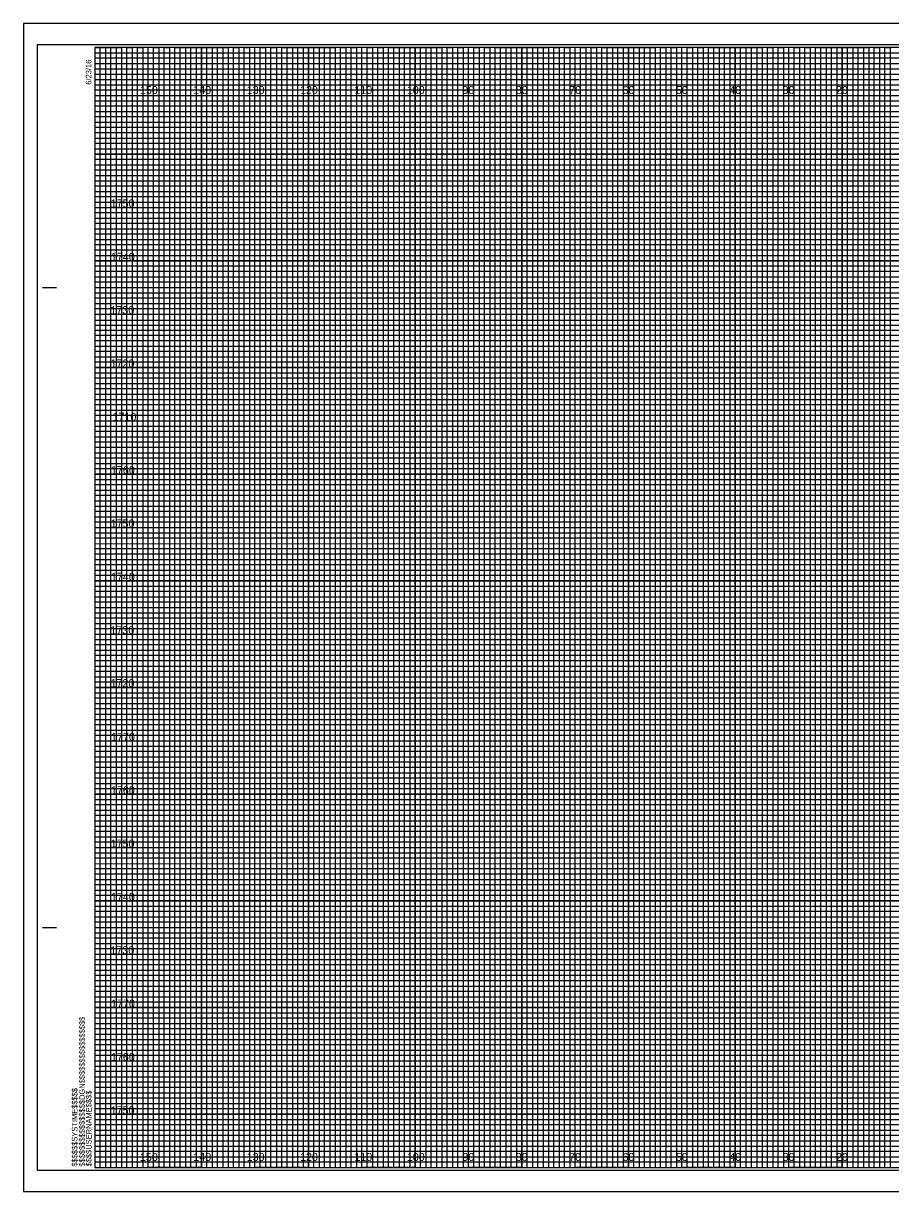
# Model space of a CAD drawing. Extents: x 570 to 907, y -9 to 870.
# Drawn here: x 570.4 to 732.9, y -9.4 to 209.6 of the extents above; entities that cross this region are included whole.
import ezdxf

# ---------------------------------------------------------------- set-up
doc = ezdxf.new("R2010")
doc.units = 0
for name, color, linetype in [('Prop XS Earthwork Shape', 7, 'Continuous'), ('Raster_Level_0', 7, 'Continuous'), ('Scratch_Level_3', 7, 'Continuous'), ('Sheet Cross Section CELL', 7, 'Continuous'), ('Sheet Cross Section Grid Middle CELL', 7, 'Continuous'), ('Sheet Cross Section Grid Minor 1 CELL', 7, 'Continuous'), ('Sheet Cross Section Grid Minor 2 CELL', 7, 'Continuous'), ('Sheet Cutting Line CELL', 7, 'Continuous'), ('Sheet DOT Grid CELL', 7, 'Continuous'), ('Sheet Plot Border Inside CELL', 7, 'Continuous'), ('Sheet Plot Border Outside CELL', 7, 'Continuous')]:
    doc.layers.add(name, color=color, linetype=linetype)

msp = doc.modelspace()

# ---------------------------------------------------------------- linework, layer by layer
at = {"layer": 'Prop XS Earthwork Shape'}
for p, q in [((593.77, 205.14), (583.77, 205.14)), ((593.77, -4.86), (593.77, 205.14)), ((613.77, 205.14), (603.77, 205.14)), ((603.77, 205.14), (603.77, -4.86)), ((613.77, -4.86), (613.77, 205.14)), ((633.77, 205.14), (623.77, 205.14)), ((623.77, 205.14), (623.77, -4.86)), ((633.77, -4.86), (633.77, 205.14)), ((653.77, 205.14), (643.77, 205.14)), ((643.77, 205.14), (643.77, -4.86)), ((653.77, -4.86), (653.77, 205.14)), ((673.77, 205.14), (663.77, 205.14)), ((663.77, 205.14), (663.77, -4.86)), ((673.77, -4.86), (673.77, 205.14)), ((693.77, 205.14), (683.77, 205.14)), ((683.77, 205.14), (683.77, -4.86)), ((693.77, -4.86), (693.77, 205.14)), ((713.77, 205.14), (703.77, 205.14)), ((703.77, 205.14), (703.77, -4.86)), ((713.77, -4.86), (713.77, 205.14)), ((733.77, 205.14), (723.77, 205.14)), ((723.77, 205.14), (723.77, -4.86)), ((603.77, -4.86), (593.77, -4.86)), ((623.77, -4.86), (613.77, -4.86)), ((643.77, -4.86), (633.77, -4.86)), ((663.77, -4.86), (653.77, -4.86)), ((683.77, -4.86), (673.77, -4.86)), ((703.77, -4.86), (693.77, -4.86)), ((723.77, -4.86), (713.77, -4.86))]:
    msp.add_line(p, q, dxfattribs=at)
for points in [[(583.77, 195.14), (903.77, 195.14), (903.77, 185.14), (583.77, 185.14)], [(583.77, 175.14), (903.77, 175.14), (903.77, 165.14), (583.77, 165.14)], [(583.77, 155.14), (903.77, 155.14), (903.77, 145.14), (583.77, 145.14)], [(583.77, 135.14), (903.77, 135.14), (903.77, 125.14), (583.77, 125.14)], [(583.77, 115.14), (903.77, 115.14), (903.77, 105.14), (583.77, 105.14)], [(583.77, 95.14), (903.77, 95.14), (903.77, 85.14), (583.77, 85.14)], [(583.77, 75.14), (903.77, 75.14), (903.77, 65.14), (583.77, 65.14)], [(583.77, 55.14), (903.77, 55.14), (903.77, 45.14), (583.77, 45.14)], [(583.77, 35.14), (903.77, 35.14), (903.77, 25.14), (583.77, 25.14)], [(583.77, 15.14), (903.77, 15.14), (903.77, 5.14), (583.77, 5.14)]]:
    msp.add_lwpolyline(points, dxfattribs=at)
at = {"layer": 'Sheet Cross Section CELL'}
for p, q in [((573.97, 160.14), (576.47, 160.14)), ((574.07, 160.14), (576.57, 160.14)), ((573.97, 40.14), (576.47, 40.14)), ((574.07, 40.14), (576.57, 40.14)), ((583.77, -4.86), (583.77, -4.86)), ((583.77, -4.86), (583.77, -4.86)), ((583.77, -4.86), (583.77, -4.86)), ((583.77, -4.86), (583.77, -4.86)), ((583.77, -4.86), (583.77, -4.86)), ((583.77, -4.86), (583.77, -4.86)), ((583.77, -4.86), (583.77, -4.86))]:
    msp.add_line(p, q, dxfattribs=at)
msp.add_lwpolyline([(903.77, 205.14), (583.77, 205.14), (583.77, -4.86), (903.77, -4.86)], close=True, dxfattribs=at)
at = {"layer": 'Sheet Cross Section Grid Middle CELL'}
for points in [[(583.77, 205.14), (588.77, 205.14), (588.77, -4.86), (598.77, -4.86), (598.77, 205.14), (608.77, 205.14), (608.77, -4.86), (618.77, -4.86), (618.77, 205.14), (628.77, 205.14), (628.77, -4.86), (638.77, -4.86), (638.77, 205.14), (648.77, 205.14), (648.77, -4.86), (658.77, -4.86), (658.77, 205.14), (668.77, 205.14), (668.77, -4.86), (678.77, -4.86), (678.77, 205.14), (688.77, 205.14), (688.77, -4.86), (698.77, -4.86), (698.77, 205.14), (708.77, 205.14), (708.77, -4.86), (718.77, -4.86), (718.77, 205.14), (728.77, 205.14), (728.77, -4.86), (738.77, -4.86)], [(583.77, 200.14), (858.77, 200.14)], [(583.77, 180.14), (903.77, 180.14), (903.77, 190.14), (583.77, 190.14)], [(583.77, 160.14), (903.77, 160.14), (903.77, 170.14), (583.77, 170.14)], [(583.77, 140.14), (903.77, 140.14), (903.77, 150.14), (583.77, 150.14)], [(583.77, 120.14), (903.77, 120.14), (903.77, 130.14), (583.77, 130.14)], [(583.77, 100.14), (903.77, 100.14), (903.77, 110.14), (583.77, 110.14)], [(583.77, 80.14), (903.77, 80.14), (903.77, 90.14), (583.77, 90.14)], [(583.77, 60.14), (903.77, 60.14), (903.77, 70.14), (583.77, 70.14)], [(583.77, 40.14), (903.77, 40.14), (903.77, 50.14), (583.77, 50.14)], [(583.77, 20.14), (903.77, 20.14), (903.77, 30.14), (583.77, 30.14)], [(583.77, 0.14), (903.77, 0.14), (903.77, 10.14), (583.77, 10.14)]]:
    msp.add_lwpolyline(points, dxfattribs=at)
at = {"layer": 'Sheet Cross Section Grid Minor 1 CELL'}
for p, q in [((583.77, 204.14), (843.77, 204.14)), ((843.77, 203.12), (583.77, 203.12)), ((583.77, 203.12), (583.77, 202.14)), ((583.77, 202.14), (843.77, 202.14)), ((843.77, 201.03), (583.77, 201.03)), ((583.77, 201.03), (583.77, 199.14)), ((583.77, 199.14), (903.77, 199.14))]:
    msp.add_line(p, q, dxfattribs=at)
for points in [[(583.77, 198.14), (853.77, 198.14), (903.77, 198.14), (903.77, 197.14), (583.77, 197.14)], [(583.77, 196.14), (903.77, 196.14), (903.77, 194.14), (583.77, 194.14)], [(583.77, 193.14), (903.77, 193.14), (903.77, 192.14), (583.77, 192.12)], [(583.77, 191.14), (903.77, 191.14), (903.77, 189.14), (583.77, 189.14)], [(583.77, 188.14), (903.77, 188.14), (903.77, 187.14), (583.77, 187.14)], [(583.77, 186.14), (903.77, 186.14), (903.77, 184.14), (583.77, 184.14)], [(583.77, 183.14), (903.77, 183.14), (903.77, 182.14), (583.77, 182.14)], [(583.77, 181.14), (903.77, 181.14), (903.77, 179.14), (583.77, 179.14)], [(583.77, 178.14), (903.77, 178.14), (903.77, 177.14), (583.77, 177.14)], [(583.77, 176.14), (903.77, 176.14), (903.77, 174.14), (583.77, 174.14)], [(583.77, 173.14), (903.77, 173.14), (903.77, 172.14), (583.77, 172.14)], [(583.77, 171.14), (903.77, 171.14), (903.77, 169.09), (903.77, 168.14), (903.77, 167.14), (583.77, 167.14)], [(583.77, 169.14), (903.77, 169.14), (903.77, 168.14), (583.77, 168.14)], [(583.77, 166.14), (903.77, 166.14), (903.77, 164.14), (583.77, 164.17)], [(583.77, 164.17), (903.77, 164.14), (903.77, 163.14), (583.77, 163.14)], [(583.77, 162.14), (903.77, 162.14), (903.77, 161.14), (583.77, 161.14)], [(583.77, 159.14), (903.77, 159.14), (903.77, 158.14), (583.77, 158.14)], [(583.77, 157.14), (903.77, 157.14), (903.77, 156.14), (583.77, 156.14)], [(583.7, 154.03), (903.77, 154.03), (903.77, 153.02), (583.7, 153.02)], [(583.77, 152.14), (903.77, 152.14), (903.77, 151.14), (583.77, 151.14)], [(583.77, 149.14), (903.77, 149.14), (903.77, 148.14), (583.77, 148.14)], [(583.77, 147.14), (903.77, 147.14), (903.77, 146.14), (583.77, 146.14)], [(583.77, 144.14), (903.77, 144.14), (903.77, 143.14), (583.77, 143.14)], [(583.77, 142.14), (903.77, 142.14), (903.77, 141.14), (583.77, 141.14)], [(583.77, 139.14), (903.77, 139.14), (903.77, 138.14), (583.77, 138.14)], [(583.77, 137.14), (903.77, 137.14), (903.77, 136.14), (583.77, 136.14)], [(583.77, 134.14), (903.77, 134.14), (903.76, 133.12), (583.77, 133.14)], [(583.77, 132.14), (903.77, 132.14), (903.77, 131.14), (583.77, 131.14)], [(583.77, 129.14), (903.77, 129.14), (903.77, 128.14), (583.77, 128.14)], [(583.77, 127.14), (903.77, 127.14), (903.77, 126.14), (583.77, 126.14)], [(583.77, 124.14), (903.77, 124.14), (903.77, 123.14), (583.77, 123.14)], [(583.77, 122.14), (903.77, 122.14), (903.77, 121.14), (583.77, 121.14)], [(583.77, 119.14), (903.77, 119.14), (903.77, 118.14), (583.77, 118.14)], [(583.77, 117.14), (903.77, 117.14), (903.77, 116.14), (583.77, 116.14)], [(583.77, 114.14), (903.77, 114.14), (903.77, 113.14), (583.77, 113.14)], [(583.77, 112.13), (903.84, 112.05), (903.77, 111.14), (583.77, 111.14)], [(583.77, 109.14), (903.77, 109.14), (903.77, 108.14), (583.77, 108.14)], [(583.77, 107.14), (903.77, 107.14), (903.77, 106.14), (583.77, 106.14)], [(583.77, 104.14), (903.77, 104.14), (903.77, 103.14), (583.77, 103.14)], [(583.77, 102.14), (903.77, 102.14), (903.77, 101.14), (583.77, 101.14)], [(583.77, 99.14), (903.77, 99.14), (903.77, 98.14), (583.77, 98.14)], [(583.77, 97.14), (903.77, 97.14), (903.77, 96.14), (583.77, 96.14)], [(583.77, 94.14), (903.77, 94.14), (903.77, 93.14), (583.77, 93.14)], [(583.77, 92.14), (903.77, 92.14), (903.77, 91.14), (583.77, 91.14)], [(583.77, 89.14), (903.77, 89.14), (903.77, 88.14), (583.77, 88.14)], [(583.77, 87.14), (903.77, 87.14), (903.77, 86.14), (583.77, 86.14)], [(583.77, 84.14), (903.77, 84.14), (903.77, 83.14), (583.77, 83.14)], [(583.77, 82.14), (903.77, 82.14), (903.77, 81.14), (583.77, 81.14)], [(583.77, 79.14), (903.77, 79.14), (903.77, 78.14), (583.77, 78.14)], [(583.77, 77.14), (903.77, 77.14), (903.77, 76.14), (583.77, 76.14)], [(583.77, 74.14), (903.77, 74.14), (903.76, 73.12), (583.77, 73.14)], [(583.77, 72.14), (903.77, 72.14), (903.77, 71.14), (583.77, 71.14)], [(583.77, 69.14), (903.77, 69.14), (903.77, 68.14), (583.77, 68.14)], [(583.77, 67.14), (903.77, 67.14), (903.77, 66.14), (583.77, 66.14)], [(583.77, 64.14), (903.77, 64.14), (903.77, 63.14), (583.77, 63.14)], [(583.77, 62.14), (903.77, 62.14), (903.77, 61.14), (583.77, 61.14)], [(583.77, 59.14), (903.77, 59.14), (903.77, 58.14), (583.77, 58.14)], [(583.77, 57.14), (903.77, 57.14), (903.77, 56.14), (583.77, 56.14)], [(583.77, 54.14), (903.77, 54.14), (903.77, 53.14), (583.77, 53.14)], [(583.77, 52.13), (903.84, 52.05), (903.77, 51.14), (583.77, 51.14)], [(583.77, 49.14), (903.77, 49.14), (903.77, 48.14), (583.77, 48.14)], [(583.77, 47.14), (903.77, 47.14), (903.77, 46.14), (583.77, 46.14)], [(583.77, 44.14), (903.77, 44.14), (903.77, 43.14), (583.77, 43.14)], [(583.77, 42.14), (903.77, 42.14), (903.77, 41.14), (583.77, 41.14)], [(583.77, 39.14), (903.77, 39.14), (903.77, 38.14), (583.77, 38.14)], [(583.77, 37.14), (903.77, 37.14), (903.77, 36.14), (583.77, 36.14)], [(583.77, 34.14), (903.77, 34.14), (903.77, 33.14), (583.77, 33.14)], [(583.77, 32.14), (903.77, 32.14), (903.77, 31.14), (583.77, 31.14)], [(583.77, 29.14), (903.77, 29.14), (903.77, 28.14), (583.77, 28.14)], [(583.77, 27.14), (903.77, 27.14), (903.77, 26.14), (583.77, 26.14)], [(583.77, 24.14), (903.77, 24.14), (903.77, 23.14), (583.77, 23.14)], [(583.77, 22.14), (903.77, 22.14), (903.77, 21.14), (583.77, 21.14)], [(583.77, 19.14), (903.77, 19.14), (903.77, 18.14), (583.77, 18.14)], [(583.77, 17.14), (903.77, 17.14), (903.77, 16.14), (583.77, 16.14)], [(583.77, 14.14), (903.77, 14.14), (903.77, 13.14), (583.77, 13.14)], [(583.77, 12.14), (903.77, 12.14), (903.77, 11.14), (583.77, 11.14)], [(583.77, 9.14), (903.77, 9.14), (903.77, 8.14), (583.77, 8.14)], [(583.77, 7.14), (903.77, 7.14), (903.77, 6.14), (583.77, 6.14)], [(583.77, 4.14), (903.77, 4.14), (903.77, 3.14), (583.77, 3.14)], [(583.77, 2.14), (903.77, 2.14), (903.77, 1.14), (583.77, 1.14)], [(583.77, -0.86), (903.77, -0.86), (903.77, -1.86), (583.77, -1.86)], [(583.77, -2.86), (903.77, -2.86), (903.77, -3.86), (583.77, -3.86)]]:
    msp.add_lwpolyline(points, dxfattribs=at)
at = {"layer": 'Sheet Cross Section Grid Minor 2 CELL'}
for points in [[(583.77, -4.86), (584.77, -4.86), (584.77, 205.14), (585.77, 205.14), (585.77, -4.86)], [(585.77, -4.86), (586.77, -4.86), (586.77, 205.14), (587.77, 205.14), (587.77, -4.86)], [(588.77, -4.86), (589.77, -4.86), (589.77, 205.14), (590.77, 205.14), (590.77, -4.86)], [(590.77, -4.86), (591.77, -4.86), (591.77, 205.14), (592.77, 205.14), (592.77, -4.86)], [(593.77, -4.86), (594.77, -4.86), (594.77, 205.14), (595.77, 205.14), (595.77, -4.86)], [(595.77, -4.86), (596.77, -4.86), (596.77, 205.14), (597.77, 205.14), (597.77, -4.86)], [(598.77, -4.86), (599.77, -4.86), (599.77, 205.14), (600.77, 205.14), (600.77, -4.86)], [(600.77, -4.86), (601.77, -4.86), (601.77, 205.14), (602.77, 205.14), (602.77, -4.86)], [(603.77, -4.86), (604.77, -4.86), (604.77, 205.14), (605.77, 205.14), (605.77, -4.86)], [(605.77, -4.86), (606.77, -4.86), (606.77, 205.14), (607.77, 205.14), (607.77, -4.86)], [(608.77, -4.86), (609.77, -4.86), (609.77, 205.14), (610.77, 205.14), (610.77, -4.86)], [(610.77, -4.86), (611.77, -4.86), (611.77, 205.14), (612.77, 205.14), (612.77, -4.86)], [(613.77, -4.86), (614.77, -4.86), (614.77, 205.14), (615.77, 205.14), (615.77, -4.86)], [(615.77, -4.86), (616.77, -4.86), (616.77, 205.14), (617.77, 205.14), (617.77, -4.86)], [(618.77, -4.86), (619.77, -4.86), (619.77, 205.14), (620.77, 205.14), (620.77, -4.86)], [(620.77, -4.86), (621.77, -4.86), (621.77, 205.14), (622.77, 205.14), (622.77, -4.86)], [(623.77, -4.86), (624.77, -4.86), (624.77, 205.14), (625.77, 205.14), (625.77, -4.86)], [(625.77, -4.86), (626.77, -4.86), (626.77, 205.14), (627.77, 205.14), (627.77, -4.86)], [(628.77, -4.86), (629.77, -4.86), (629.77, 205.14), (630.77, 205.14), (630.77, -4.86)], [(630.77, -4.86), (631.77, -4.86), (631.77, 205.14), (632.77, 205.14), (632.77, -4.86)], [(633.77, -4.86), (634.77, -4.86), (634.77, 205.14), (635.77, 205.14), (635.77, -4.86)], [(635.77, -4.86), (636.77, -4.86), (636.77, 205.14), (637.77, 205.14), (637.77, -4.86)], [(638.77, -4.86), (639.77, -4.86), (639.77, 205.14), (640.77, 205.14), (640.77, -4.86)], [(640.77, -4.86), (641.77, -4.86), (641.77, 205.14), (642.77, 205.14), (642.77, -4.86)], [(643.77, -4.86), (644.77, -4.86), (644.77, 205.14), (645.77, 205.14), (645.77, -4.86)], [(645.77, -4.86), (646.77, -4.86), (646.77, 205.14), (647.77, 205.14), (647.77, -4.86)], [(648.77, -4.86), (649.77, -4.86), (649.77, 205.14), (650.77, 205.14), (650.77, -4.86)], [(650.77, -4.86), (651.77, -4.86), (651.77, 205.14), (652.77, 205.14), (652.77, -4.86)], [(653.77, -4.86), (654.77, -4.86), (654.77, 205.14), (655.77, 205.14), (655.77, -4.86)], [(655.77, -4.86), (656.77, -4.86), (656.77, 205.14), (657.77, 205.14), (657.77, -4.86)], [(658.77, -4.86), (659.77, -4.86), (659.77, 205.14), (660.77, 205.14), (660.77, -4.86)], [(660.77, -4.86), (661.77, -4.86), (661.77, 205.14), (662.77, 205.14), (662.77, -4.86)], [(663.77, -4.86), (664.77, -4.86), (664.77, 205.14), (665.77, 205.14), (665.77, -4.86)], [(665.77, -4.86), (666.77, -4.86), (666.77, 205.14), (667.77, 205.14), (667.77, -4.86)], [(668.77, -4.86), (669.77, -4.86), (669.77, 205.14), (670.77, 205.14), (670.77, -4.86)], [(670.77, -4.86), (671.77, -4.86), (671.77, 205.14), (672.77, 205.14), (672.77, -4.86)], [(673.77, -4.86), (674.77, -4.86), (674.77, 205.14), (675.77, 205.14), (675.77, -4.86)], [(675.77, -4.86), (676.77, -4.86), (676.77, 205.14), (677.77, 205.14), (677.77, -4.86)], [(678.77, -4.86), (679.77, -4.86), (679.77, 205.14), (680.77, 205.14), (680.77, -4.86)], [(680.77, -4.86), (681.77, -4.86), (681.77, 205.14), (682.77, 205.14), (682.77, -4.86)], [(683.77, -4.86), (684.77, -4.86), (684.77, 205.14), (685.77, 205.14), (685.77, -4.86)], [(685.77, -4.86), (686.77, -4.86), (686.77, 205.14), (687.77, 205.14), (687.77, -4.86)], [(688.77, -4.86), (689.77, -4.86), (689.77, 205.14), (690.77, 205.14), (690.77, -4.86)], [(690.77, -4.86), (691.77, -4.86), (691.77, 205.14), (692.77, 205.14), (692.77, -4.86)], [(693.77, -4.86), (694.77, -4.86), (694.77, 205.14), (695.77, 205.14), (695.77, -4.86)], [(695.77, -4.86), (696.77, -4.86), (696.77, 205.14), (697.77, 205.14), (697.77, -4.86)], [(698.77, -4.86), (699.77, -4.86), (699.77, 205.14), (700.77, 205.14), (700.77, -4.86)], [(700.77, -4.86), (701.77, -4.86), (701.77, 205.14), (702.77, 205.14), (702.77, -4.86)], [(703.77, -4.86), (704.77, -4.86), (704.77, 205.14), (705.77, 205.14), (705.77, -4.86)], [(705.77, -4.86), (706.77, -4.86), (706.77, 205.14), (707.77, 205.14), (707.77, -4.86)], [(708.77, -4.86), (709.77, -4.86), (709.77, 205.14), (710.77, 205.14), (710.77, -4.86)], [(710.77, -4.86), (711.77, -4.86), (711.77, 205.14), (712.77, 205.14), (712.77, -4.86)], [(713.77, -4.86), (714.77, -4.86), (714.77, 205.14), (715.77, 205.14), (715.77, -4.86)], [(715.77, -4.86), (716.77, -4.86), (716.77, 205.14), (717.77, 205.14), (717.77, -4.86)], [(718.77, -4.86), (719.77, -4.86), (719.77, 205.14), (720.77, 205.14), (720.77, -4.86)], [(720.77, -4.86), (721.77, -4.86), (721.77, 205.14), (722.77, 205.14), (722.77, -4.86)], [(723.77, -4.86), (724.77, -4.86), (724.77, 205.14), (725.77, 205.14), (725.77, -4.86)], [(725.77, -4.86), (726.77, -4.86), (726.77, 205.14), (727.77, 205.14), (727.77, -4.86)], [(728.77, -4.86), (729.77, -4.86), (729.77, 205.14), (730.77, 205.14), (730.77, -4.86)], [(730.77, -4.86), (731.77, -4.86), (731.77, 205.14), (732.77, 205.14), (732.77, -4.86)]]:
    msp.add_lwpolyline(points, dxfattribs=at)
at = {"layer": 'Sheet Cutting Line CELL'}
for p, q in [((907.07, 209.64), (570.37, 209.64)), ((570.37, 209.64), (570.37, -9.36)), ((570.37, -9.36), (907.07, -9.36))]:
    msp.add_line(p, q, dxfattribs=at)
at = {"layer": 'Sheet DOT Grid CELL'}
for p, q in [((593.77, -4.86), (593.77, 205.14)), ((603.77, -4.86), (603.77, 205.14)), ((613.77, -4.86), (613.77, 205.14)), ((623.77, -4.86), (623.77, 205.14)), ((633.77, -4.86), (633.77, 205.14)), ((643.77, -4.86), (643.77, 205.14)), ((653.77, -4.86), (653.77, 205.14)), ((663.77, -4.86), (663.77, 205.14)), ((673.77, -4.86), (673.77, 205.14)), ((683.77, -4.86), (683.77, 205.14)), ((693.77, -4.86), (693.77, 205.14)), ((703.77, -4.86), (703.77, 205.14)), ((713.77, -4.86), (713.77, 205.14)), ((723.77, -4.86), (723.77, 205.14)), ((583.77, 195.14), (903.77, 195.14)), ((583.77, 185.14), (903.77, 185.14)), ((583.77, 175.14), (903.77, 175.14)), ((583.77, 165.14), (903.77, 165.14)), ((583.77, 155.14), (903.77, 155.14)), ((583.77, 145.14), (903.77, 145.14)), ((583.77, 135.14), (903.77, 135.14)), ((583.77, 125.14), (903.77, 125.14)), ((583.77, 115.14), (903.77, 115.14)), ((583.77, 105.14), (903.77, 105.14)), ((583.77, 95.14), (903.77, 95.14)), ((583.77, 85.14), (903.77, 85.14)), ((583.77, 75.14), (903.77, 75.14)), ((583.77, 65.14), (903.77, 65.14)), ((583.77, 55.14), (903.77, 55.14)), ((583.77, 45.14), (903.77, 45.14)), ((583.77, 35.14), (903.77, 35.14)), ((583.77, 25.14), (903.77, 25.14)), ((583.77, 15.14), (903.77, 15.14)), ((583.77, 5.14), (903.77, 5.14))]:
    msp.add_line(p, q, dxfattribs=at)
at = {"layer": 'Sheet Plot Border Inside CELL'}
msp.add_lwpolyline([(572.97, -5.36), (906.17, -5.36), (906.17, 205.64), (572.97, 205.64)], close=True, dxfattribs=at)
at = {"layer": 'Sheet Plot Border Outside CELL'}
msp.add_lwpolyline([(570.37, -9.36), (907.07, -9.36), (907.07, 209.64), (570.37, 209.64)], close=True, dxfattribs=at)

# ---------------------------------------------------------------- texts
at = {"layer": 'Raster_Level_0'}
for s, p in [('150', (592.22, 196.39)), ('140', (602.22, 196.39)), ('130', (612.22, 196.39)), ('120', (622.22, 196.39)), ('110', (632.4, 196.39)), ('100', (642.22, 196.39)), ('90', (652.63, 196.39)), ('80', (662.63, 196.39)), ('70', (672.63, 196.39)), ('60', (682.63, 196.39)), ('50', (692.63, 196.39)), ('40', (702.63, 196.39)), ('30', (712.63, 196.39)), ('20', (722.63, 196.39)), ('150', (592.22, -3.61)), ('140', (602.22, -3.61)), ('130', (612.22, -3.61)), ('120', (622.22, -3.61)), ('110', (632.4, -3.61)), ('100', (642.22, -3.61)), ('90', (652.63, -3.61)), ('80', (662.63, -3.61)), ('70', (672.63, -3.61)), ('60', (682.63, -3.61)), ('50', (692.63, -3.61)), ('40', (702.63, -3.61)), ('30', (712.63, -3.61)), ('20', (722.63, -3.61))]:
    msp.add_text(s, height=1.5, dxfattribs=at).set_placement(p)
at = {"layer": 'Scratch_Level_3'}
for s, p in [('1750', (586.73, 175.14)), ('1740', (586.78, 165.14)), ('1730', (586.69, 155.14)), ('1720', (586.71, 145.14)), ('1710', (587.08, 135.14)), ('1760', (586.78, 125.14)), ('1750', (586.73, 115.14)), ('1740', (586.78, 105.14)), ('1730', (586.69, 95.14)), ('1720', (586.71, 85.22)), ('1770', (586.81, 75.14)), ('1760', (586.78, 65.14)), ('1750', (586.73, 55.14)), ('1740', (586.78, 45.14)), ('1730', (586.69, 35.14)), ('1770', (586.81, 25.14)), ('1760', (586.78, 15.14)), ('1750', (586.73, 5.14))]:
    msp.add_text(s, height=1.5, dxfattribs=at).set_placement(p)
at = {"layer": 'Sheet Cross Section CELL'}
for s, p in [('6/23/16', (583.12, 198.14)), ('$$$$$$$$$$$$$$$$DGN$$$$$$$$$$$$$$$$', (581.89, -4.68)), ('$$$$$$SYSTIME$$$$$', (580.51, -4.68)), ('$$$$USERNAME$$$$', (583.15, -4.63))]:
    msp.add_text(s, height=1.05, rotation=90, dxfattribs=at).set_placement(p)

doc.saveas('drawing.dxf')
